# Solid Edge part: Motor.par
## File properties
Author: CADCIM
Template: NORMENG.PAR
Last saved by: CADCIM
Revision: 4
Application: Solid Edge
Density: 0 lbm/in^3
Accuracy: 0.99
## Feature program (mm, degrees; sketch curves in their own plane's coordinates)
sketch for "unnamed Protrusion 1" plane through (0, 0, 0) normal (0, -1, 0) x-axis (1, 0, 0)
  line (-152.4, 0) -> (152.4, 0)
  line (152.4, 0) -> (83.1942, 183.7359)
  line (-152.4, 0) -> (-83.1942, 183.7359)
  dimension (linear) = 152.4
extrude "unnamed Protrusion 1" add finite 165.1 along -normal
sketch for "ExtrudedProtrusion_2" plane through (0, 165.1, 120.65) normal (0, 1, 0) x-axis (-1, 0, 0)
  circle centre (0, 31.75) radius 88.9
extrude "ExtrudedProtrusion_2" add finite 57.15 along +normal
sketch for "ExtrudedProtrusion_3" plane through (0, 222.25, 152.4) normal (0, 1, 0) x-axis (-1, 0, 0)
  circle centre (0, 0) radius 127
extrude "ExtrudedProtrusion_3" add finite 12.7 along +normal
sketch for "ExtrudedProtrusion_4" plane through (0, 222.25, 152.4) normal (0, -1, 0) x-axis (1, 0, 0)
  line (-76.2, 25.4) -> (76.2, 25.4)
  line (76.2, 25.4) -> (76.2, 152.4)
  line (76.2, 152.4) -> (-76.2, 152.4)
  line (-76.2, 152.4) -> (-76.2, 25.4)
  dimension (linear) = 76.2
  dimension (linear) = 76.2
extrude "ExtrudedProtrusion_4" add finite 203.2 along +normal
sketch for "unnamed Cutout 1" plane through (0, 19.05, 251.4953) normal (0, -1, 0) x-axis (1, 0, 0)
  line (-76.2, 41.8747) -> (-63.5, 41.8747)
  line (-63.5, 41.8747) -> (-63.5, 30.4447)
  line (-63.5, 30.4447) -> (-76.2, 30.4447)
  line (-76.2, 30.4447) -> (-76.2, 41.8747)
  dimension (linear) = 76.2
  dimension (linear) = 76.2
  dimension (linear) = 63.5
extrude "unnamed Cutout 1" cut along +normal
pattern "unnamed Pattern 1" of "unnamed Cutout 1"
extrude "unnamed Cutout 2" cut
extrude "unnamed Cutout 3" cut
extrude "unnamed Cutout 4" cut
extrude "unnamed Cutout 5" cut
extrude "unnamed Cutout 6" cut
extrude "unnamed Cutout 7" cut
extrude "unnamed Cutout 8" cut
sketch for "Hole_1" plane through (0, 234.95, 152.4) normal (0, 1, 0) x-axis (-1, 0, 0)
  hole centre (0, 0) bore radius 76.2
hole "Hole_1" diameter 152.4 finite
sketch for "Hole_2" plane through (0, 0, 120.65) normal (0, -1, 0) x-axis (1, 0, 0)
  hole centre (0, 31.75) bore radius 19.05
hole "Hole_2" diameter 38.1 through
sketch for "Hole_3" plane through (0, 234.95, 152.4) normal (0, 1, 0) x-axis (-1, 0, 0)
  hole centre (0, -107.95) bore radius 9.525
hole "Hole_3" diameter 19.05 through
pattern "unnamed Pattern 2" of "Hole_3"
pattern "unnamed Pattern 3"
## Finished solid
Body 1: solid body, 60 faces, 151 edges, 90 vertices.
  Faces by surface: plane 53, cylinder 7
  Edges by curve: line 126, circle 25
Bounding box of the edges (mm): 304.800 x 234.950 x 304.800, from (-152.4, 0, 0) to (152.4, 234.95, 304.8).
Cylindrical faces by radius (mm): R9.525 x3, R19.05 x1, R76.2 x1, R88.9 x1, R127 x1
Planar faces by outward normal: +x 9, +y 8, +z 9, -x 9, -y 7, -z 9, oblique 2
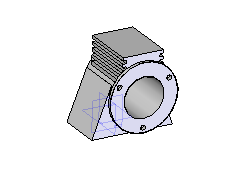
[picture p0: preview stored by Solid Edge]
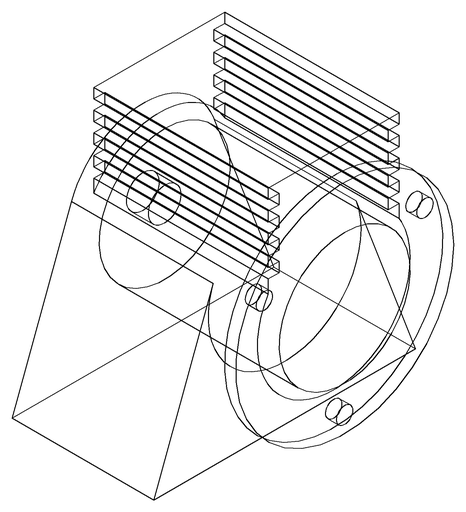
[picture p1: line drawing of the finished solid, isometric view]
